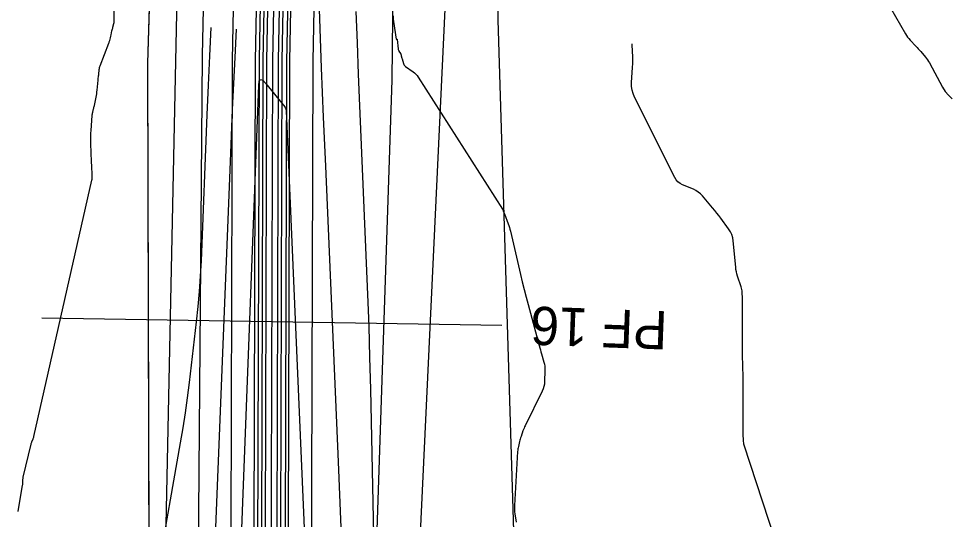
# Model space of a CAD drawing. Extents: x -534410 to -534262, y -1190162 to -1189584.
# Drawn here: x -534372.92 to -534348.65, y -1189760.85 to -1189747.77 of the extents above; entities that cross this region are included whole.
import ezdxf

# ---------------------------------------------------------------- set-up
doc = ezdxf.new("R2010")
doc.units = 0
for name, color, linetype in [('30', 7, 'Continuous'), ('31', 7, 'Continuous'), ('_linie', 7, 'Continuous'), ('_N_osa', 7, 'Continuous'), ('_N_tenká', 7, 'Continuous'), ('_N_tenká_velmi', 7, 'Continuous'), ('_N_text', 7, 'Continuous'), ('_tenka', 7, 'Continuous'), ('Default', 7, 'Continuous'), ('Hranice parcel', 7, 'Continuous')]:
    doc.layers.add(name, color=color, linetype=linetype)

msp = doc.modelspace()

# ---------------------------------------------------------------- linework, layer by layer
at = {"layer": '30'}
for points in [[(-534364.125, -1189747.582), (-534364.096, -1189748.404), (-534364.065, -1189749.225), (-534364.032, -1189750.047), (-534363.997, -1189750.869), (-534363.856, -1189754.155), (-534363.822, -1189754.977), (-534363.793, -1189755.799), (-534363.769, -1189756.621), (-534363.748, -1189757.443), (-534363.663, -1189761.251)], [(-534369.28, -1189762.169), (-534368.697, -1189758.85), (-534368.631, -1189758.457), (-534368.57, -1189758.063), (-534368.515, -1189757.668), (-534368.466, -1189757.272), (-534368.281, -1189755.687), (-534368.239, -1189755.29), (-534368.204, -1189754.893), (-534368.177, -1189754.495), (-534368.157, -1189754.097), (-534368.005, -1189750.281), (-534367.973, -1189749.512), (-534367.937, -1189748.743), (-534367.9, -1189748.004)], [(-534353.033, -1189761.861), (-534353.994, -1189758.911), (-534354.004, -1189758.878), (-534354.011, -1189758.844), (-534354.016, -1189758.809), (-534354.018, -1189758.774), (-534354.022, -1189758.633), (-534354.023, -1189758.598), (-534354.024, -1189758.563), (-534354.024, -1189758.528), (-534354.025, -1189758.493), (-534354.025, -1189757.196), (-534354.025, -1189757.161), (-534354.025, -1189757.126), (-534354.026, -1189757.091), (-534354.027, -1189757.056), (-534354.031, -1189756.915), (-534354.033, -1189756.88), (-534354.034, -1189756.844), (-534354.035, -1189756.809), (-534354.036, -1189756.774), (-534354.04, -1189756.62), (-534354.041, -1189756.583), (-534354.042, -1189756.545), (-534354.042, -1189756.508), (-534354.042, -1189756.471), (-534354.042, -1189755.218), (-534354.042, -1189755.181), (-534354.043, -1189755.144), (-534354.043, -1189755.106), (-534354.044, -1189755.069), (-534354.049, -1189754.919), (-534354.051, -1189754.882), (-534354.057, -1189754.845), (-534354.064, -1189754.809), (-534354.075, -1189754.774), (-534354.169, -1189754.496), (-534354.187, -1189754.437), (-534354.201, -1189754.378), (-534354.212, -1189754.318), (-534354.22, -1189754.257), (-534354.285, -1189753.574), (-534354.298, -1189753.49), (-534354.322, -1189753.41), (-534354.357, -1189753.334), (-534354.403, -1189753.263), (-534354.606, -1189752.984), (-534354.658, -1189752.915), (-534354.711, -1189752.847), (-534354.765, -1189752.779), (-534354.82, -1189752.713), (-534355.086, -1189752.401), (-534355.138, -1189752.347), (-534355.195, -1189752.3), (-534355.257, -1189752.26), (-534355.324, -1189752.227), (-534355.603, -1189752.111), (-534355.669, -1189752.077), (-534355.725, -1189752.033), (-534355.772, -1189751.98), (-534355.811, -1189751.917), (-534356.857, -1189749.82), (-534356.895, -1189749.73), (-534356.921, -1189749.637), (-534356.934, -1189749.541), (-534356.934, -1189749.442), (-534356.911, -1189749.044), (-534356.906, -1189748.944), (-534356.904, -1189748.844), (-534356.905, -1189748.745), (-534356.908, -1189748.645), (-534356.918, -1189748.428)], [(-534367.558, -1189773.027), (-534367.512, -1189771.753), (-534366.662, -1189749.511), (-534366.647, -1189749.405), (-534366.611, -1189749.36), (-534366.556, -1189749.375), (-534366.481, -1189749.452), (-534365.983, -1189750.077), (-534365.978, -1189750.084), (-534365.973, -1189750.092), (-534365.968, -1189750.1), (-534365.964, -1189750.108), (-534365.95, -1189750.142), (-534365.947, -1189750.15), (-534365.945, -1189750.159), (-534365.943, -1189750.168), (-534365.943, -1189750.177), (-534365.213, -1189767.124), (-534365.16, -1189768.439), (-534365.113, -1189769.753), (-534365.074, -1189771.067), (-534365.041, -1189772.382), (-534364.917, -1189777.897), (-534364.89, -1189779.084)]]:
    msp.add_lwpolyline(points, dxfattribs=at)
at = {"layer": '31'}
for points in [[(-534365.123, -1189746.489), (-534365.076, -1189747.773), (-534365.028, -1189749.058), (-534364.976, -1189750.342), (-534364.922, -1189751.626), (-534364.59, -1189759.346), (-534364.52, -1189761.061), (-534364.46, -1189762.776), (-534364.408, -1189764.492), (-534364.365, -1189766.207), (-534364.12, -1189777.185), (-534364.111, -1189777.327), (-534364.093, -1189777.468), (-534364.065, -1189777.607), (-534364.026, -1189777.744), (-534363.833, -1189778.351), (-534363.802, -1189778.458), (-534363.774, -1189778.566), (-534363.752, -1189778.675), (-534363.733, -1189778.785), (-534363.639, -1189779.439)], [(-534350.183, -1189747.485), (-534349.794, -1189748.168), (-534349.767, -1189748.212), (-534349.738, -1189748.254), (-534349.706, -1189748.294), (-534349.671, -1189748.333), (-534349.521, -1189748.488), (-534349.488, -1189748.523), (-534349.456, -1189748.558), (-534349.425, -1189748.593), (-534349.394, -1189748.629), (-534349.271, -1189748.773), (-534349.241, -1189748.809), (-534349.213, -1189748.847), (-534349.188, -1189748.887), (-534349.164, -1189748.928), (-534348.823, -1189749.558), (-534348.753, -1189749.671), (-534348.67, -1189749.773), (-534348.574, -1189749.863)], [(-534372.934, -1189760.639), (-534372.819, -1189759.949), (-534372.816, -1189759.932), (-534372.815, -1189759.915), (-534372.813, -1189759.898), (-534372.812, -1189759.88), (-534372.811, -1189759.812), (-534372.81, -1189759.795), (-534372.808, -1189759.778), (-534372.806, -1189759.761), (-534372.802, -1189759.744), (-534372.597, -1189758.878), (-534372.593, -1189758.862), (-534372.588, -1189758.845), (-534372.582, -1189758.829), (-534372.576, -1189758.813), (-534372.548, -1189758.749), (-534372.541, -1189758.733), (-534372.535, -1189758.717), (-534372.53, -1189758.7), (-534372.526, -1189758.683), (-534371.012, -1189751.986), (-534371.007, -1189751.959), (-534371.003, -1189751.931), (-534371.002, -1189751.903), (-534371.002, -1189751.875), (-534371.008, -1189751.762), (-534371.011, -1189751.706), (-534371.014, -1189751.65), (-534371.023, -1189751.481), (-534371.025, -1189751.443), (-534371.026, -1189751.406), (-534371.028, -1189751.368), (-534371.029, -1189751.331), (-534371.041, -1189750.977), (-534371.042, -1189750.906), (-534371.041, -1189750.835), (-534371.039, -1189750.763), (-534371.034, -1189750.692), (-534371.004, -1189750.303), (-534371.002, -1189750.28), (-534370.999, -1189750.258), (-534370.995, -1189750.237), (-534370.99, -1189750.215), (-534370.968, -1189750.128), (-534370.963, -1189750.107), (-534370.958, -1189750.085), (-534370.953, -1189750.063), (-534370.948, -1189750.042), (-534370.902, -1189749.82), (-534370.893, -1189749.776), (-534370.886, -1189749.731), (-534370.88, -1189749.686), (-534370.875, -1189749.641), (-534370.851, -1189749.381), (-534370.85, -1189749.369), (-534370.849, -1189749.356), (-534370.847, -1189749.344), (-534370.846, -1189749.331), (-534370.839, -1189749.281), (-534370.838, -1189749.269), (-534370.836, -1189749.256), (-534370.835, -1189749.244), (-534370.834, -1189749.231), (-534370.821, -1189749.101), (-534370.817, -1189749.075), (-534370.812, -1189749.05), (-534370.805, -1189749.025), (-534370.797, -1189749), (-534370.571, -1189748.413), (-534370.564, -1189748.395), (-534370.558, -1189748.378), (-534370.553, -1189748.36), (-534370.548, -1189748.341), (-534370.53, -1189748.269), (-534370.522, -1189748.232), (-534370.513, -1189748.196), (-534370.488, -1189748.087), (-534370.482, -1189748.063), (-534370.476, -1189748.04), (-534370.47, -1189748.016), (-534370.464, -1189747.992), (-534370.44, -1189747.896), (-534370.435, -1189747.872), (-534370.431, -1189747.848), (-534370.429, -1189747.824), (-534370.428, -1189747.799), (-534370.428, -1189747.571)], [(-534363.158, -1189747.696), (-534363.15, -1189747.773), (-534363.141, -1189747.849), (-534363.078, -1189748.303), (-534363.077, -1189748.306), (-534363.076, -1189748.308), (-534363.074, -1189748.309), (-534363.071, -1189748.309), (-534363.059, -1189748.308), (-534363.056, -1189748.308), (-534363.055, -1189748.309), (-534363.053, -1189748.311), (-534363.053, -1189748.313), (-534363.023, -1189748.56), (-534363.021, -1189748.576), (-534363.016, -1189748.59), (-534363.01, -1189748.604), (-534363.002, -1189748.618), (-534362.96, -1189748.682), (-534362.956, -1189748.689), (-534362.952, -1189748.697), (-534362.95, -1189748.704), (-534362.948, -1189748.713), (-534362.942, -1189748.751), (-534362.941, -1189748.757), (-534362.94, -1189748.762), (-534362.938, -1189748.768), (-534362.937, -1189748.774), (-534362.927, -1189748.803), (-534362.922, -1189748.82), (-534362.886, -1189748.946), (-534362.878, -1189748.968), (-534362.867, -1189748.987), (-534362.852, -1189749.004), (-534362.834, -1189749.019), (-534362.635, -1189749.16), (-534362.597, -1189749.19), (-534362.563, -1189749.222), (-534362.532, -1189749.259), (-534362.504, -1189749.298), (-534360.302, -1189752.749), (-534360.297, -1189752.758), (-534360.292, -1189752.767), (-534360.287, -1189752.776), (-534360.283, -1189752.786), (-534360.264, -1189752.835), (-534360.257, -1189752.854), (-534360.253, -1189752.864), (-534360.155, -1189753.127), (-534360.138, -1189753.174), (-534360.123, -1189753.222), (-534360.109, -1189753.27), (-534360.097, -1189753.319), (-534359.834, -1189754.449), (-534359.787, -1189754.647), (-534359.738, -1189754.845), (-534359.688, -1189755.042), (-534359.635, -1189755.238), (-534359.345, -1189756.309), (-534359.33, -1189756.363), (-534359.315, -1189756.417), (-534359.3, -1189756.47), (-534359.284, -1189756.524), (-534359.222, -1189756.738), (-534359.209, -1189756.791), (-534359.2, -1189756.846), (-534359.195, -1189756.9), (-534359.195, -1189756.956), (-534359.204, -1189757.246), (-534359.21, -1189757.312), (-534359.222, -1189757.376), (-534359.241, -1189757.438), (-534359.267, -1189757.499), (-534359.71, -1189758.4), (-534359.726, -1189758.433), (-534359.741, -1189758.467), (-534359.755, -1189758.501), (-534359.768, -1189758.536), (-534359.819, -1189758.683), (-534359.83, -1189758.715), (-534359.84, -1189758.747), (-534359.849, -1189758.779), (-534359.857, -1189758.811), (-534359.888, -1189758.94), (-534359.895, -1189758.973), (-534359.901, -1189759.005), (-534359.905, -1189759.038), (-534359.907, -1189759.071), (-534359.989, -1189760.482), (-534359.991, -1189760.537), (-534359.989, -1189760.592), (-534359.986, -1189760.647), (-534359.979, -1189760.702), (-534359.946, -1189760.921)], [(-534368.254, -1189773.003), (-534367.398, -1189751.502), (-534367.341, -1189750.144), (-534367.279, -1189748.788), (-534367.241, -1189748.042)]]:
    msp.add_lwpolyline(points, dxfattribs=at)
at = {"layer": '_linie'}
for points in [[(-534366.12, -1189620.81), (-534364.52, -1189627.2), (-534365.69, -1189653.8), (-534366.76, -1189684.81), (-534368.14, -1189748.73), (-534368.38, -1189779.14), (-534368.65, -1189820.64), (-534368.59, -1189847.58), (-534367.2, -1189913.8)], [(-534363.12, -1189621.02), (-534362.79, -1189621.58), (-534361.82, -1189627.79), (-534363.46, -1189653.55), (-534365.47, -1189684.77), (-534366.65, -1189748.83), (-534366.75, -1189779.47), (-534366.9, -1189820.47), (-534366.95, -1189846.72), (-534366.338, -1189888.804), (-534363.85, -1189911.95), (-534357.07, -1189929.19), (-534352.334, -1189940.856)], [(-534359.03, -1189621.26), (-534359.41, -1189621.83), (-534360.84, -1189627.76), (-534362.92, -1189653.56), (-534364.64, -1189685), (-534365.94, -1189748.9), (-534366.02, -1189779.52), (-534366.03, -1189820.5), (-534366.48, -1189846.73), (-534365.511, -1189888.873), (-534362.72, -1189912.12), (-534356.62, -1189928.64), (-534351.589, -1189940.594)]]:
    msp.add_lwpolyline(points, dxfattribs=at)
at = {"layer": '_N_osa'}
msp.add_lwpolyline([(-534351.95, -1189940.722), (-534356.845, -1189928.915), (-534363.285, -1189912.035), (-534365.925, -1189888.838), (-534366.715, -1189846.725), (-534366.465, -1189820.485), (-534366.385, -1189779.495), (-534366.295, -1189748.865), (-534365.055, -1189684.885), (-534363.19, -1189653.555), (-534361.333, -1189627.822)], dxfattribs=at)
at = {"layer": '_N_tenká'}
for points in [[(-534352.92, -1189941.124), (-534357.821, -1189929.303), (-534364.313, -1189912.285), (-534366.973, -1189888.908), (-534367.765, -1189846.73), (-534367.515, -1189820.479), (-534367.435, -1189779.492), (-534367.345, -1189748.853), (-534366.104, -1189684.844), (-534364.238, -1189653.486), (-534362.424, -1189628.352), (-534361.782, -1189627.792)], [(-534352.089, -1189940.779), (-534356.984, -1189928.97), (-534363.432, -1189912.071), (-534366.074, -1189888.848), (-534366.865, -1189846.726), (-534366.615, -1189820.484), (-534366.535, -1189779.495), (-534366.445, -1189748.863), (-534365.205, -1189684.879), (-534363.34, -1189653.545), (-534361.483, -1189627.812)], [(-534351.812, -1189940.664), (-534356.706, -1189928.86), (-534363.138, -1189911.999), (-534365.775, -1189888.828), (-534366.565, -1189846.724), (-534366.315, -1189820.486), (-534366.235, -1189779.495), (-534366.145, -1189748.867), (-534364.905, -1189684.891), (-534363.04, -1189653.565), (-534361.184, -1189627.831)], [(-534350.98, -1189940.319), (-534355.869, -1189928.527), (-534362.257, -1189911.785), (-534364.876, -1189888.769), (-534365.665, -1189846.72), (-534365.415, -1189820.491), (-534365.335, -1189779.498), (-534365.245, -1189748.877), (-534364.006, -1189684.926), (-534362.142, -1189653.624), (-534360.329, -1189628.488), (-534360.884, -1189627.851)]]:
    msp.add_lwpolyline(points, dxfattribs=at)
at = {"layer": '_N_tenká_velmi'}
for points in [[(-534352.366, -1189940.894), (-534357.263, -1189929.081), (-534363.726, -1189912.142), (-534366.374, -1189888.868), (-534367.165, -1189846.727), (-534366.915, -1189820.482), (-534366.835, -1189779.494), (-534366.745, -1189748.86), (-534365.505, -1189684.867), (-534363.639, -1189653.525), (-534361.782, -1189627.792)], [(-534352.181, -1189940.817), (-534357.077, -1189929.007), (-534363.53, -1189912.095), (-534366.174, -1189888.855), (-534366.965, -1189846.726), (-534366.715, -1189820.484), (-534366.635, -1189779.494), (-534366.545, -1189748.862), (-534365.305, -1189684.875), (-534363.439, -1189653.539), (-534361.583, -1189627.805)], [(-534351.719, -1189940.626), (-534356.613, -1189928.823), (-534363.04, -1189911.975), (-534365.675, -1189888.822), (-534366.465, -1189846.724), (-534366.215, -1189820.486), (-534366.135, -1189779.496), (-534366.045, -1189748.868), (-534364.805, -1189684.895), (-534362.941, -1189653.571), (-534361.084, -1189627.838)], [(-534351.534, -1189940.549), (-534356.427, -1189928.749), (-534362.844, -1189911.928), (-534365.475, -1189888.808), (-534366.265, -1189846.723), (-534366.015, -1189820.488), (-534365.935, -1189779.496), (-534365.845, -1189748.87), (-534364.605, -1189684.903), (-534362.741, -1189653.585), (-534360.884, -1189627.851)]]:
    msp.add_lwpolyline(points, dxfattribs=at)
at = {"layer": '_N_text'}
msp.add_lwpolyline([(-534360.316, -1189755.786), (-534372.314, -1189755.591)], dxfattribs=at)
at = {"layer": '_tenka'}
for points in [[(-534349.13, -1189939.73), (-534354.63, -1189926.96), (-534362.03, -1189907.65), (-534364.521, -1189888.74), (-534364.47, -1189846.64), (-534364.29, -1189820.63), (-534364.22, -1189780.69), (-534363.18, -1189749.38), (-534362.5, -1189685.39), (-534360.27, -1189651.6), (-534357.03, -1189627.34), (-534354.77, -1189620.37)], [(-534366.12, -1189620.81), (-534364.52, -1189627.2), (-534365.69, -1189653.8), (-534366.76, -1189684.81), (-534368.14, -1189748.73), (-534368.38, -1189779.14), (-534368.65, -1189820.64), (-534368.59, -1189847.58), (-534367.2, -1189913.8)], [(-534366.12, -1189620.81), (-534364.52, -1189627.2), (-534365.69, -1189653.8), (-534366.76, -1189684.81), (-534368.14, -1189748.73), (-534368.38, -1189779.14), (-534368.65, -1189820.64), (-534368.59, -1189847.58), (-534367.2, -1189913.8)], [(-534363.12, -1189621.02), (-534362.79, -1189621.58), (-534361.82, -1189627.79), (-534363.46, -1189653.55), (-534365.47, -1189684.77), (-534366.65, -1189748.83), (-534366.75, -1189779.47), (-534366.9, -1189820.47), (-534366.95, -1189846.72), (-534366.338, -1189888.804), (-534363.85, -1189911.95), (-534357.07, -1189929.19), (-534352.334, -1189940.856)], [(-534363.12, -1189621.02), (-534362.79, -1189621.58), (-534361.82, -1189627.79), (-534363.46, -1189653.55), (-534365.47, -1189684.77), (-534366.65, -1189748.83), (-534366.75, -1189779.47), (-534366.9, -1189820.47), (-534366.95, -1189846.72), (-534366.338, -1189888.804), (-534363.85, -1189911.95), (-534357.07, -1189929.19), (-534352.334, -1189940.856)], [(-534359.03, -1189621.26), (-534359.41, -1189621.83), (-534360.84, -1189627.76), (-534362.92, -1189653.56), (-534364.64, -1189685), (-534365.94, -1189748.9), (-534366.02, -1189779.52), (-534366.03, -1189820.5), (-534366.48, -1189846.73), (-534365.511, -1189888.873), (-534362.72, -1189912.12), (-534356.62, -1189928.64), (-534351.589, -1189940.594)], [(-534359.03, -1189621.26), (-534359.41, -1189621.83), (-534360.84, -1189627.76), (-534362.92, -1189653.56), (-534364.64, -1189685), (-534365.94, -1189748.9), (-534366.02, -1189779.52), (-534366.03, -1189820.5), (-534366.48, -1189846.73), (-534365.511, -1189888.873), (-534362.72, -1189912.12), (-534356.62, -1189928.64), (-534351.589, -1189940.594)], [(-534368.65, -1189626.81), (-534368.65, -1189626.81), (-534367.31, -1189654.04), (-534367.67, -1189685.23), (-534369.56, -1189748.93), (-534369.48, -1189778.6), (-534369.45, -1189820.62), (-534369.45, -1189847.87), (-534371.206, -1189896.071), (-534372.39, -1189914.47)]]:
    msp.add_lwpolyline(points, dxfattribs=at)
at = {"layer": 'Default'}
for p, q in [((-534367.67, -1189685.23), (-534369.56, -1189748.93)), ((-534369.56, -1189748.93), (-534369.48, -1189778.6))]:
    msp.add_line(p, q, dxfattribs=at)
msp.add_lwpolyline([(-534349.13, -1189939.73), (-534354.63, -1189926.96), (-534362.03, -1189907.65), (-534364.521, -1189888.74), (-534364.47, -1189846.64), (-534364.29, -1189820.63), (-534364.22, -1189780.69), (-534363.18, -1189749.38), (-534362.5, -1189685.39), (-534360.27, -1189651.6), (-534357.03, -1189627.34), (-534354.77, -1189620.37)], dxfattribs=at)
at = {"layer": 'Hranice parcel'}
msp.add_line((-534369.14, -1189764.19), (-534367.77, -1189697.34), dxfattribs=at)
for points in [[(-534359.48, -1189697.97), (-534362.6, -1189764.35), (-534362.34, -1189901.56)], [(-534359.48, -1189697.97), (-534360.42, -1189747.8), (-534359.17, -1189788.69), (-534356.86, -1189843.2), (-534358.53, -1189915.98)]]:
    msp.add_lwpolyline(points, dxfattribs=at)

# ---------------------------------------------------------------- texts
at = {"layer": '_N_text'}
msp.add_text('PF 16', height=1, rotation=177.8926, dxfattribs=at).set_placement((-534355.982, -1189755.414))

doc.saveas('drawing.dxf')
